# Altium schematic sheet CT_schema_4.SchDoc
size 218 x 258 mm
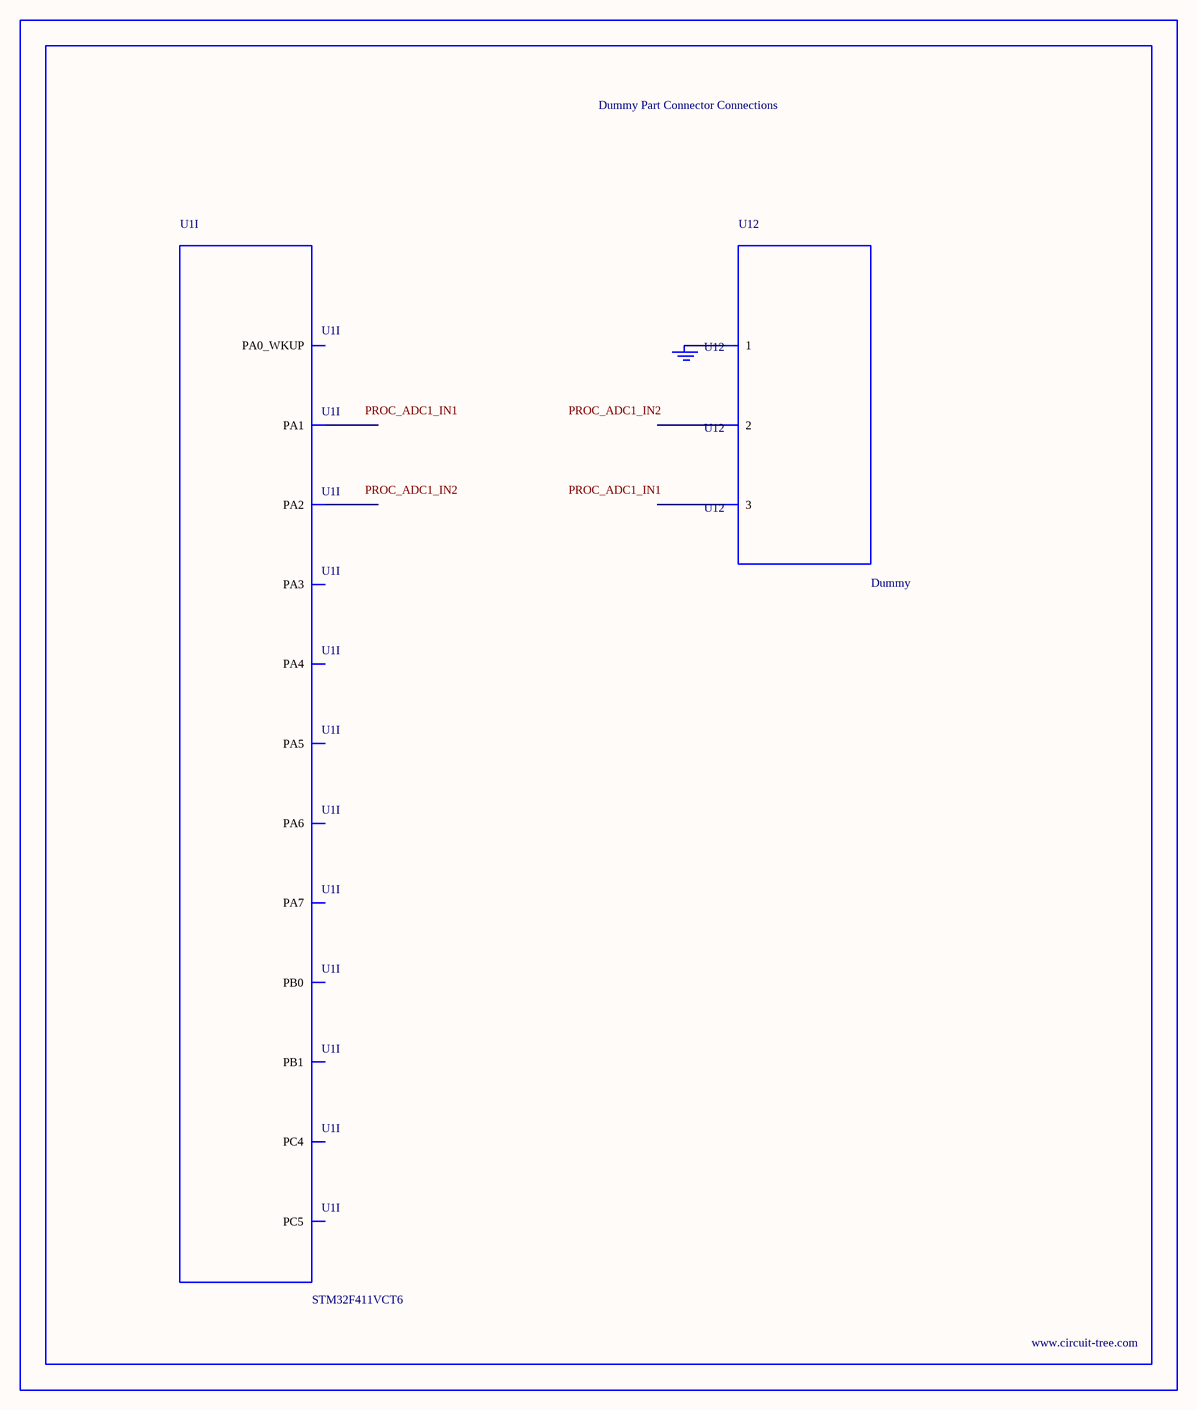
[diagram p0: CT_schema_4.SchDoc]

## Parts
BORDER3  (no value)
GND_INSTANCE_3_0  (no value)
U1  STM32F411VCT6  [LQFP100]  (part I of 9)
U12  Dummy  [DUMMY_PACKAGE_121]

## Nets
NetGND_INSTANCE_3_0_0: GND_INSTANCE_3_0.0(GND) U12.1

Not connected (* = marked no-connect by the designer): U1 23(PA0_WKUP) 24(PA1) 25(PA2) 26(PA3) 29(PA4) 30(PA5) 31(PA6) 32(PA7) 33(PC4) 34(PC5) 35(PB0) 36(PB1); U12 2 3

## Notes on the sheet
- Labels drawn without touching a wire or pin: PROC_ADC1_IN1, PROC_ADC1_IN2

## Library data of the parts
BORDER3 = BORDER_PAGE3
GND_INSTANCE_3_0 = GND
